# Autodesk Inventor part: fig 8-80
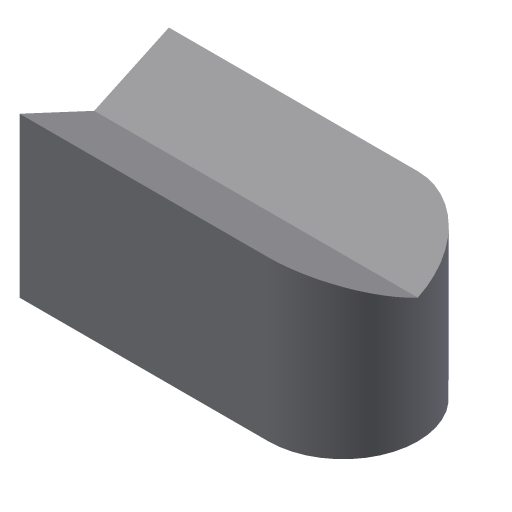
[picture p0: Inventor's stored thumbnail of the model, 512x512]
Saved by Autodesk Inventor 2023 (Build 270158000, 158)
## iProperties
Created: 2011-07
Part Number: fig 8-80
Material: Generic
Document SubType Name: Modeling
Designer: CadCim
Density: 1 g/cm^3
Appearance: Default
Author: CadCim
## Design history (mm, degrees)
sketch "Sketch1"
  geometry: L1 (-16, 5)-(-16, -7); L2 (-16, -7)-(4, -7); L3 (4, 5)-(-16, 5); A1 r 6 centre (4, -1) between (4, -7) and (4, 5); 1 further point
  constraints: 6 end point, 2 point on circle, 2 tangent, 1 centre point, 1 parallel, 1 perpendicular, 1 vertical
extrude "Extrusion1" new body sketch "Sketch1" distance "d0" = 10; taper "d1" = 0 deg
sketch "Sketch2"
  geometry: L1 (-16, -1)-(10, -1); 1 further point
  constraints: 2 end point, 1 horizontal
feature "FaceDraft1" sketch "Sketch2" dims angle "d2" = -25 deg
body "Solid1"
